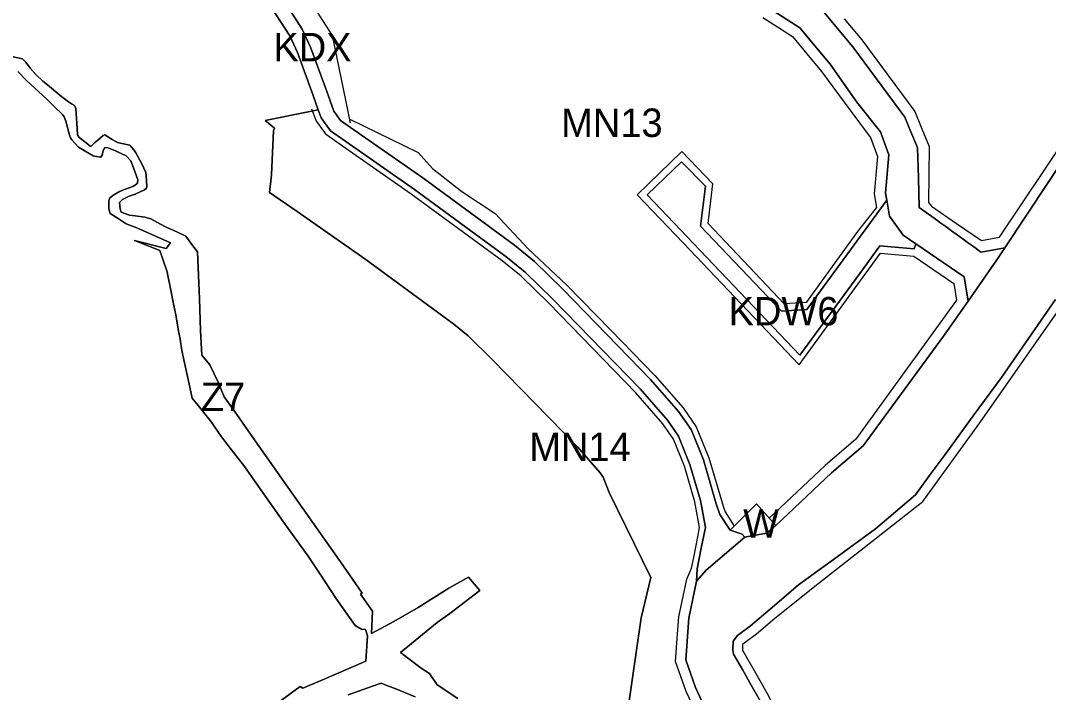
# Model space of a CAD drawing. Extents: x 7439486 to 7443435, y 5551288 to 5554556.
# Drawn here: x 7440456.7 to 7440818.3, y 5552471.7 to 5552708 of the extents above; entities that cross this region are included whole.
import ezdxf

# ---------------------------------------------------------------- set-up
doc = ezdxf.new("R2010")
doc.units = 0
for name, color, linetype in [('linie_rozgraniczajace', 7, 'Continuous'), ('linie_zabudowy_nieprzekraczalne', 7, 'Continuous'), ('oznaczenia_przeznaczen', 7, 'Continuous')]:
    doc.layers.add(name, color=color, linetype=linetype)

msp = doc.modelspace()

# ---------------------------------------------------------------- linework, layer by layer
at = {"layer": 'linie_rozgraniczajace'}
for points in [[(7440541.58, 5552717.93), (7440551.41, 5552702.61), (7440554.12, 5552696.79), (7440559.59, 5552681.66), (7440561.4, 5552676.66), (7440559.07, 5552676.16), (7440542.74, 5552672.85), (7440545.97, 5552670.17), (7440545.64, 5552669.3), (7440545.02, 5552653.81), (7440544.28, 5552647.58), (7440553.96, 5552640.84), (7440577.84, 5552624.21), (7440609.1, 5552601.28), (7440614.21, 5552597.15), (7440622.66, 5552588.85), (7440652.61, 5552558.12), (7440660.56, 5552548.99), (7440661.66, 5552547.41), (7440663.83, 5552542.08), (7440678.45, 5552512.1), (7440674.99, 5552497.99), (7440670.23, 5552464.67)], [(7440692.22, 5552551.91), (7440688.19, 5552561.8), (7440684.26, 5552567.46), (7440674.68, 5552578.46), (7440643.92, 5552610.02), (7440634.2, 5552619.57), (7440627.42, 5552625.05), (7440595.29, 5552648.62), (7440571.1, 5552665.46), (7440565.7, 5552669.22), (7440562.42, 5552673.83), (7440561.4, 5552676.66), (7440559.59, 5552681.66), (7440554.12, 5552696.79), (7440551.41, 5552702.61), (7440541.58, 5552717.93)], [(7440720.13, 5552712.42), (7440730.92, 5552705.44), (7440741.55, 5552692.7), (7440750.97, 5552679.36), (7440759.26, 5552668.89), (7440762.24, 5552660.79), (7440761.07, 5552647.28), (7440761.48, 5552644.88), (7440733.38, 5552606.36), (7440724.44, 5552605.81), (7440695.94, 5552635.73), (7440697.68, 5552649.76), (7440689.29, 5552658.38), (7440677.13, 5552646.68), (7440730.89, 5552590.29), (7440751.93, 5552619.01), (7440759.05, 5552628.82), (7440771.13, 5552627.69), (7440771.72, 5552629.46), (7440788.69, 5552617.83), (7440790.09, 5552609.37), (7440781.47, 5552596.97), (7440761.85, 5552570.27), (7440753.14, 5552558.42), (7440742.07, 5552548.97), (7440722.38, 5552530.42), (7440715.65, 5552538.08), (7440706.37, 5552528.77), (7440702.76, 5552534.32), (7440701.4, 5552538.09), (7440696.95, 5552553.55), (7440692.62, 5552564.2), (7440688.21, 5552570.54), (7440678.36, 5552581.84), (7440647.46, 5552613.54), (7440637.54, 5552623.3), (7440630.47, 5552629.01), (7440598.2, 5552652.69), (7440573.96, 5552669.56), (7440569.27, 5552672.82), (7440566.89, 5552676.17), (7440564.29, 5552683.36), (7440558.75, 5552698.69), (7440555.8, 5552705.02), (7440545.55, 5552721)], [(7440545.55, 5552721), (7440555.8, 5552705.02), (7440558.75, 5552698.69), (7440564.29, 5552683.36), (7440566.89, 5552676.17), (7440569.27, 5552672.82), (7440573.96, 5552669.56), (7440598.2, 5552652.69), (7440630.47, 5552629.01), (7440637.54, 5552623.3), (7440647.46, 5552613.54), (7440678.36, 5552581.84), (7440688.21, 5552570.54), (7440692.62, 5552564.2), (7440696.95, 5552553.55), (7440701.4, 5552538.09), (7440702.76, 5552534.32), (7440706.37, 5552528.77), (7440708.46, 5552528.05), (7440710.54, 5552527.34), (7440711.47, 5552526.33), (7440697.93, 5552514.68), (7440694.51, 5552510.83), (7440694.76, 5552515.16), (7440696.21, 5552522.42), (7440697.66, 5552529.68), (7440695.88, 5552539.18), (7440692.22, 5552551.91)], [(7440737.63, 5552713.01), (7440749.48, 5552698.79), (7440767.79, 5552674.04), (7440769.95, 5552668.83), (7440771.87, 5552664.21), (7440772.28, 5552663.22), (7440772.59, 5552652.75), (7440772.9, 5552642.29), (7440773.7, 5552641.71), (7440774.51, 5552641.13), (7440775.32, 5552640.54), (7440777.35, 5552639.08), (7440779.37, 5552637.62), (7440780.18, 5552637.03), (7440782.21, 5552635.57), (7440784.24, 5552634.11), (7440785.05, 5552633.52), (7440787.08, 5552632.06), (7440789.11, 5552630.6), (7440789.92, 5552630.01), (7440791.95, 5552628.55), (7440793.97, 5552627.09), (7440794.73, 5552626.55), (7440802.95, 5552628.05), (7440800.2, 5552623.91), (7440790.09, 5552609.37), (7440788.69, 5552617.83), (7440771.72, 5552629.46), (7440767.23, 5552632.54), (7440762.44, 5552639.23), (7440761.48, 5552644.88), (7440761.07, 5552647.28), (7440762.24, 5552660.79), (7440759.26, 5552668.89), (7440750.97, 5552679.36), (7440741.55, 5552692.7), (7440730.92, 5552705.44), (7440720.13, 5552712.42)], [(7440833.02, 5552673.38), (7440802.95, 5552628.05), (7440794.73, 5552626.55), (7440793.97, 5552627.09), (7440791.95, 5552628.55), (7440789.92, 5552630.01), (7440789.11, 5552630.6), (7440787.08, 5552632.06), (7440785.05, 5552633.52), (7440784.24, 5552634.11), (7440782.21, 5552635.57), (7440780.18, 5552637.03), (7440779.37, 5552637.62), (7440777.35, 5552639.08), (7440775.32, 5552640.54), (7440774.51, 5552641.13), (7440773.7, 5552641.71), (7440772.9, 5552642.29), (7440772.59, 5552652.75), (7440772.28, 5552663.22), (7440771.87, 5552664.21), (7440769.95, 5552668.83), (7440767.79, 5552674.04), (7440749.48, 5552698.79), (7440737.63, 5552713.01)], [(7440600.52, 5552478.43), (7440597.62, 5552480.32), (7440590.33, 5552485.8), (7440603.26, 5552496.35), (7440607.71, 5552499.54), (7440618.25, 5552507.59), (7440614.24, 5552512.24), (7440607.31, 5552508.39), (7440596.61, 5552501.58), (7440588.06, 5552496.68), (7440580.14, 5552492.44), (7440580.24, 5552495.12), (7440580.45, 5552500.31), (7440576.3, 5552506.28), (7440576.85, 5552506.66), (7440576.61, 5552507), (7440569.23, 5552517.63), (7440567.22, 5552520.48), (7440539.25, 5552560.21), (7440532.01, 5552570.6), (7440528.32, 5552575.71), (7440526.18, 5552580.85), (7440523.29, 5552586.94), (7440520.4, 5552590.38), (7440520.04, 5552599.05), (7440519.63, 5552610.11), (7440519.4, 5552615.7), (7440518.94, 5552626.64), (7440517.26, 5552628.82), (7440514.85, 5552632.22), (7440511.62, 5552633.67), (7440507.95, 5552635.32), (7440505.96, 5552636.42), (7440502.46, 5552638.34), (7440500.42, 5552638.84), (7440497, 5552639.29), (7440494.98, 5552639.63), (7440492.13, 5552640.62), (7440491.69, 5552641.86), (7440491.51, 5552644.08), (7440492.58, 5552645.07), (7440494.91, 5552646.22), (7440496.97, 5552646.97), (7440500.34, 5552648.49), (7440500.96, 5552649.12), (7440501.11, 5552649.63), (7440500.88, 5552653.58), (7440500.71, 5552654.58), (7440499.33, 5552657.62), (7440497.24, 5552661.55), (7440496.51, 5552662.6), (7440495.07, 5552664.23), (7440492.32, 5552664.81), (7440490.73, 5552665.16), (7440488.95, 5552666.24), (7440486.28, 5552667.87), (7440485.71, 5552667.61), (7440483.83, 5552666), (7440482.7, 5552665.04), (7440481.53, 5552663.89), (7440481.19, 5552663.85), (7440479.77, 5552664.97), (7440477.34, 5552666.87), (7440476.72, 5552667.87), (7440476.59, 5552670.04), (7440476.16, 5552677.04), (7440475.63, 5552678.14), (7440474.59, 5552678.77), (7440473.59, 5552679.46), (7440471.16, 5552681.16), (7440466.13, 5552685.36), (7440464.49, 5552686.72), (7440462.01, 5552689.01), (7440460.04, 5552691.31), (7440458.51, 5552693.43), (7440457.3, 5552694.53), (7440452.39, 5552695.59)], [(7440452.39, 5552695.59), (7440457.3, 5552694.53), (7440458.51, 5552693.43), (7440460.04, 5552691.31), (7440462.01, 5552689.01), (7440464.49, 5552686.72), (7440466.13, 5552685.36), (7440471.16, 5552681.16), (7440473.59, 5552679.46), (7440474.59, 5552678.77), (7440475.63, 5552678.14), (7440476.16, 5552677.04), (7440476.59, 5552670.04), (7440476.72, 5552667.87), (7440477.34, 5552666.87), (7440479.77, 5552664.97), (7440481.19, 5552663.85), (7440481.53, 5552663.89), (7440482.7, 5552665.04), (7440483.83, 5552666), (7440485.71, 5552667.61), (7440486.28, 5552667.87), (7440488.95, 5552666.24), (7440490.73, 5552665.16), (7440492.32, 5552664.81), (7440495.07, 5552664.23), (7440496.51, 5552662.6), (7440497.24, 5552661.55), (7440499.33, 5552657.62), (7440500.71, 5552654.58), (7440500.88, 5552653.58), (7440501.11, 5552649.63), (7440500.96, 5552649.12), (7440500.34, 5552648.49), (7440496.97, 5552646.97), (7440494.91, 5552646.22), (7440492.58, 5552645.07), (7440491.51, 5552644.08), (7440491.69, 5552641.86), (7440492.13, 5552640.62), (7440494.98, 5552639.63), (7440497, 5552639.29), (7440500.42, 5552638.84), (7440502.46, 5552638.34), (7440505.96, 5552636.42), (7440507.95, 5552635.32), (7440511.62, 5552633.67), (7440514.85, 5552632.22), (7440517.26, 5552628.82), (7440518.94, 5552626.64), (7440519.4, 5552615.7), (7440519.63, 5552610.11), (7440520.04, 5552599.05), (7440520.4, 5552590.38), (7440523.29, 5552586.94), (7440526.18, 5552580.85), (7440528.32, 5552575.71), (7440532.01, 5552570.6), (7440539.25, 5552560.21), (7440567.22, 5552520.48), (7440569.23, 5552517.63), (7440576.61, 5552507), (7440576.85, 5552506.66), (7440576.3, 5552506.28), (7440580.45, 5552500.31), (7440580.24, 5552495.12), (7440580.14, 5552492.44), (7440588.06, 5552496.68), (7440596.61, 5552501.58), (7440607.31, 5552508.39), (7440614.24, 5552512.24), (7440618.25, 5552507.59), (7440607.71, 5552499.54)], [(7440455.74, 5552690.05), (7440458.77, 5552686.94), (7440466.06, 5552680.23), (7440468.6, 5552677.72), (7440471.39, 5552674.97), (7440472.03, 5552674.14), (7440472.65, 5552672.62), (7440473.91, 5552667.69), (7440474.3, 5552666.73), (7440474.73, 5552666.1), (7440477.09, 5552663.48), (7440479.06, 5552662.29), (7440482.18, 5552660.42), (7440483.44, 5552660.2), (7440484.89, 5552659.96), (7440485.35, 5552660.65), (7440485.78, 5552662.18), (7440486.26, 5552663.2), (7440487.14, 5552663.32), (7440490.12, 5552662.2), (7440493.87, 5552660.4), (7440495.45, 5552658.66), (7440496.47, 5552656.23), (7440497.93, 5552651.96), (7440497.78, 5552650.92), (7440497.44, 5552650.47), (7440496.18, 5552649.69), (7440493.6, 5552648.77), (7440491.53, 5552647.84), (7440489.52, 5552646.78), (7440488.06, 5552645.67), (7440487.72, 5552644.63), (7440487.69, 5552641.85), (7440488.21, 5552640.2), (7440491.03, 5552638.36), (7440493.86, 5552636.52), (7440497.57, 5552635.16), (7440509.47, 5552629.85), (7440507.9, 5552627.81), (7440496.76, 5552630.62), (7440505.67, 5552627.16), (7440508.23, 5552619.63), (7440508.48, 5552618.37), (7440509.4, 5552613.73), (7440510.57, 5552607.78), (7440511.3, 5552604.48), (7440512.08, 5552599.53), (7440512.78, 5552595.92), (7440513.41, 5552591.95), (7440514.35, 5552587.68), (7440516.25, 5552579.06), (7440517.09, 5552575.27), (7440519.14, 5552572.62), (7440523.89, 5552566.78), (7440527.04, 5552562.09), (7440530.95, 5552557.06), (7440533.38, 5552553.94), (7440535.19, 5552551.52), (7440539.54, 5552545.36), (7440549.93, 5552530.66), (7440557.92, 5552519.62), (7440562.04, 5552513.36), (7440567.6, 5552504.9), (7440574.37, 5552495.27)], [(7440486.26, 5552663.2), (7440485.78, 5552662.18), (7440485.35, 5552660.65), (7440484.89, 5552659.96), (7440483.44, 5552660.2), (7440482.18, 5552660.42), (7440479.06, 5552662.29), (7440477.09, 5552663.48), (7440474.73, 5552666.1), (7440474.3, 5552666.73), (7440473.91, 5552667.69), (7440472.65, 5552672.62), (7440472.03, 5552674.14), (7440471.39, 5552674.97), (7440468.6, 5552677.72), (7440466.06, 5552680.23), (7440458.77, 5552686.94), (7440455.74, 5552690.05)], [(7440670.23, 5552464.67), (7440674.99, 5552497.99), (7440678.45, 5552512.1), (7440663.83, 5552542.08), (7440661.66, 5552547.41), (7440660.56, 5552548.99), (7440652.61, 5552558.12), (7440622.66, 5552588.85), (7440614.21, 5552597.15), (7440609.1, 5552601.28), (7440577.84, 5552624.21), (7440553.96, 5552640.84), (7440544.28, 5552647.58), (7440545.02, 5552653.81), (7440545.64, 5552669.3), (7440545.97, 5552670.17), (7440542.74, 5552672.85), (7440559.07, 5552676.16), (7440561.4, 5552676.66), (7440562.42, 5552673.83), (7440565.7, 5552669.22), (7440571.1, 5552665.46), (7440595.29, 5552648.62), (7440627.42, 5552625.05), (7440634.2, 5552619.57), (7440643.92, 5552610.02), (7440674.68, 5552578.46), (7440684.26, 5552567.46), (7440688.19, 5552561.8), (7440692.22, 5552551.91), (7440695.88, 5552539.18), (7440697.66, 5552529.68), (7440696.21, 5552522.42), (7440694.76, 5552515.16), (7440694.51, 5552510.83), (7440691.76, 5552497.8), (7440690.72, 5552483.14), (7440694.17, 5552473.42), (7440699.41, 5552462.15)], [(7440690.72, 5552483.14), (7440691.76, 5552497.8), (7440694.51, 5552510.83), (7440697.93, 5552514.68), (7440711.47, 5552526.33), (7440712.15, 5552526.42), (7440719.18, 5552527.7), (7440721.1, 5552529.22), (7440722.38, 5552530.42), (7440742.07, 5552548.97), (7440753.14, 5552558.42), (7440761.85, 5552570.27), (7440781.47, 5552596.97), (7440790.09, 5552609.37), (7440800.2, 5552623.91), (7440802.95, 5552628.05), (7440833.02, 5552673.38)], [(7440548.03, 5552468.66), (7440555.1, 5552473.84), (7440555.98, 5552473.21), (7440561.89, 5552475.73), (7440578.15, 5552482.68), (7440578.71, 5552491.65), (7440578.02, 5552493.85), (7440576.6, 5552493.99), (7440574.37, 5552495.27), (7440567.6, 5552504.9), (7440562.04, 5552513.36), (7440557.92, 5552519.62), (7440549.93, 5552530.66), (7440539.54, 5552545.36), (7440535.19, 5552551.52), (7440533.38, 5552553.94), (7440530.95, 5552557.06), (7440527.04, 5552562.09), (7440523.89, 5552566.78), (7440519.14, 5552572.62), (7440517.09, 5552575.27), (7440516.25, 5552579.06), (7440514.35, 5552587.68), (7440513.41, 5552591.95), (7440512.78, 5552595.92), (7440512.08, 5552599.53), (7440511.3, 5552604.48), (7440510.57, 5552607.78), (7440509.4, 5552613.73), (7440508.48, 5552618.37), (7440508.23, 5552619.63), (7440505.67, 5552627.16), (7440496.76, 5552630.62), (7440507.9, 5552627.81), (7440509.47, 5552629.85), (7440497.57, 5552635.16), (7440493.86, 5552636.52), (7440491.03, 5552638.36), (7440488.21, 5552640.2), (7440487.69, 5552641.85), (7440487.72, 5552644.63), (7440488.06, 5552645.67), (7440489.52, 5552646.78), (7440491.53, 5552647.84), (7440493.6, 5552648.77), (7440496.18, 5552649.69), (7440497.44, 5552650.47), (7440497.78, 5552650.92), (7440497.93, 5552651.96), (7440496.47, 5552656.23), (7440495.45, 5552658.66), (7440493.87, 5552660.4), (7440490.12, 5552662.2), (7440487.14, 5552663.32), (7440486.26, 5552663.2)], [(7440707.27, 5552486.63), (7440707.4, 5552489.75), (7440708.88, 5552491.71), (7440713.5, 5552495.1), (7440721.94, 5552502.36), (7440730.38, 5552509.62), (7440743.96, 5552519.47), (7440757.54, 5552529.31), (7440764.55, 5552535.3), (7440771.57, 5552541.28), (7440776.78, 5552548.37), (7440781.99, 5552555.46), (7440791.9, 5552568.95), (7440801.81, 5552582.43), (7440811.34, 5552596.15), (7440820.88, 5552609.86)], [(7440820.88, 5552609.86), (7440811.34, 5552596.15), (7440801.81, 5552582.43), (7440791.9, 5552568.95), (7440781.99, 5552555.46), (7440776.78, 5552548.37), (7440771.57, 5552541.28), (7440764.55, 5552535.3), (7440757.54, 5552529.31), (7440743.96, 5552519.47), (7440730.38, 5552509.62), (7440721.94, 5552502.36), (7440713.5, 5552495.1), (7440708.88, 5552491.71), (7440707.4, 5552489.75), (7440707.27, 5552486.63), (7440707.54, 5552485.24), (7440710.66, 5552479.76), (7440713.78, 5552474.29), (7440716.91, 5552468.82)], [(7440607.71, 5552499.54), (7440603.26, 5552496.35), (7440590.33, 5552485.8), (7440597.62, 5552480.32), (7440600.52, 5552478.43), (7440603.26, 5552474.45), (7440610.5, 5552469.61)], [(7440574.37, 5552495.27), (7440576.6, 5552493.99), (7440578.02, 5552493.85), (7440578.71, 5552491.65), (7440578.15, 5552482.68), (7440561.89, 5552475.73), (7440555.98, 5552473.21), (7440555.1, 5552473.84), (7440548.03, 5552468.66)], [(7440812.35, 5552232.97), (7440810.86, 5552244.81), (7440809.37, 5552256.65), (7440807.54, 5552266.86), (7440805.7, 5552277.08), (7440804.44, 5552282.56), (7440803.19, 5552288.05), (7440801.19, 5552293.97), (7440799.19, 5552299.9), (7440796.24, 5552306.03), (7440793.29, 5552312.17), (7440780.71, 5552338.32), (7440768.13, 5552364.47), (7440754.63, 5552391.46), (7440741.12, 5552418.46), (7440729.01, 5552443.64), (7440716.91, 5552468.82), (7440713.78, 5552474.29), (7440710.66, 5552479.76), (7440707.54, 5552485.24), (7440707.27, 5552486.63)], [(7440699.41, 5552462.15), (7440694.17, 5552473.42), (7440690.72, 5552483.14)], [(7440610.5, 5552469.61), (7440603.26, 5552474.45), (7440600.52, 5552478.43)], [(7440571.93, 5552470.9), (7440582.46, 5552474.6), (7440583.68, 5552474.97), (7440585.22, 5552474.31), (7440588.16, 5552473.21), (7440595.48, 5552470.23)], [(7440595.48, 5552470.23), (7440588.16, 5552473.21), (7440585.22, 5552474.31), (7440583.68, 5552474.97), (7440582.46, 5552474.6), (7440571.93, 5552470.9)]]:
    msp.add_lwpolyline(points, dxfattribs=at)
for points in [[(7440677.13, 5552646.68), (7440689.29, 5552658.38), (7440697.68, 5552649.76), (7440695.94, 5552635.73), (7440724.44, 5552605.81), (7440733.38, 5552606.36), (7440761.48, 5552644.88), (7440762.44, 5552639.23), (7440767.23, 5552632.54), (7440771.72, 5552629.46), (7440771.13, 5552627.69), (7440759.05, 5552628.82), (7440751.93, 5552619.01), (7440730.89, 5552590.29)], [(7440706.37, 5552528.77), (7440715.65, 5552538.08), (7440722.38, 5552530.42), (7440721.1, 5552529.22), (7440719.18, 5552527.7), (7440712.15, 5552526.42), (7440711.47, 5552526.33), (7440710.54, 5552527.34), (7440708.46, 5552528.05)]]:
    msp.add_lwpolyline(points, close=True, dxfattribs=at)
at = {"layer": 'linie_zabudowy_nieprzekraczalne'}
for points in [[(7440820.32, 5552197.72), (7440815.07, 5552239.39), (7440811.79, 5552259.94), (7440808.51, 5552280.49), (7440806.56, 5552289), (7440803.45, 5552298.21), (7440790.9, 5552325.21), (7440764.52, 5552379.51), (7440742.31, 5552424.31), (7440726.11, 5552457.74), (7440720.01, 5552470.44), (7440715.43, 5552478.46), (7440710.86, 5552486.47), (7440710.78, 5552486.89), (7440710.86, 5552488.83), (7440715.68, 5552492.36), (7440722.02, 5552497.81), (7440737.23, 5552509.98), (7440774.12, 5552538.84), (7440794.17, 5552566.49), (7440831.37, 5552619.67), (7440910.95, 5552737.79), (7440979.56, 5552840.3), (7441030.3, 5552920.28)], [(7440539.41, 5552742.31), (7440539.01, 5552738.12), (7440540.7, 5552734.4), (7440543.93, 5552730.28), (7440548.44, 5552725.16), (7440559.05, 5552713.19), (7440561.07, 5552711), (7440566.29, 5552702.8), (7440572.6, 5552671.99), (7440572.58, 5552673.36), (7440596.55, 5552661.58), (7440601.67, 5552655.98), (7440611.96, 5552647.95), (7440623.63, 5552640.2), (7440635.29, 5552627.69), (7440648.86, 5552614.97), (7440664.34, 5552599.09), (7440679.83, 5552583.2), (7440689.79, 5552571.77), (7440694.38, 5552565.16), (7440698.84, 5552554.21), (7440703.98, 5552536.83), (7440704.57, 5552535.21), (7440707.81, 5552530.22)], [(7440717.87, 5552709.12), (7440723.05, 5552705.76), (7440728.24, 5552702.41), (7440733.35, 5552696.27), (7440738.47, 5552690.14), (7440746.52, 5552679.26), (7440754.56, 5552668.38), (7440755.73, 5552666.9), (7440758.18, 5552660.24), (7440757.04, 5552647.11), (7440757.86, 5552642.31), (7440751.55, 5552634.27), (7440742.3, 5552621.58), (7440733.05, 5552608.9), (7440725.41, 5552608.42), (7440698.57, 5552636.6), (7440700.3, 5552650.64), (7440689.35, 5552661.91), (7440673.6, 5552646.75), (7440689.79, 5552629.87), (7440730.67, 5552586.96), (7440759.31, 5552626.24), (7440770.94, 5552625.15), (7440785.03, 5552615.5), (7440785.99, 5552609.69), (7440750.56, 5552560.82), (7440739.73, 5552551.57), (7440720.07, 5552533.05)], [(7440746.47, 5552708.65), (7440752.63, 5552701.26), (7440761.96, 5552688.65), (7440771.29, 5552676.03), (7440773.84, 5552669.89), (7440776.39, 5552663.76), (7440776.29, 5552653.91), (7440776.2, 5552644.06), (7440777.17, 5552642.69), (7440785.98, 5552636.66), (7440794.79, 5552630.63), (7440801.18, 5552631.79), (7440842.09, 5552692.97)], [(7440696.24, 5552460.68), (7440690.93, 5552472.1), (7440687.18, 5552482.66), (7440687.75, 5552490.72), (7440688.29, 5552498.29), (7440691.09, 5552511.59), (7440692.78, 5552515.41), (7440693.53, 5552519.18), (7440694.97, 5552526.44), (7440695.62, 5552529.69), (7440693.94, 5552538.72), (7440690.32, 5552551.25), (7440686.42, 5552560.84), (7440682.68, 5552566.23), (7440673.21, 5552577.1), (7440642.5, 5552608.6), (7440632.87, 5552618.07), (7440626.19, 5552623.47), (7440594.13, 5552646.99), (7440569.96, 5552663.82), (7440564.27, 5552667.77), (7440560.64, 5552672.89), (7440559.2, 5552676.87)]]:
    msp.add_lwpolyline(points, dxfattribs=at)

# ---------------------------------------------------------------- texts
at = {"layer": 'oznaczenia_przeznaczen'}
for s, p in [('KDX', (7440545.64, 5552693.69)), ('MN13', (7440646.91, 5552667.07)), ('KDW6', (7440705.82, 5552600.81)), ('Z7', (7440520.13, 5552570.71)), ('MN14', (7440635.68, 5552553.12)), ('W', (7440710.93, 5552526.17))]:
    msp.add_text(s, height=10, dxfattribs=at).set_placement(p)

doc.saveas('drawing.dxf')
